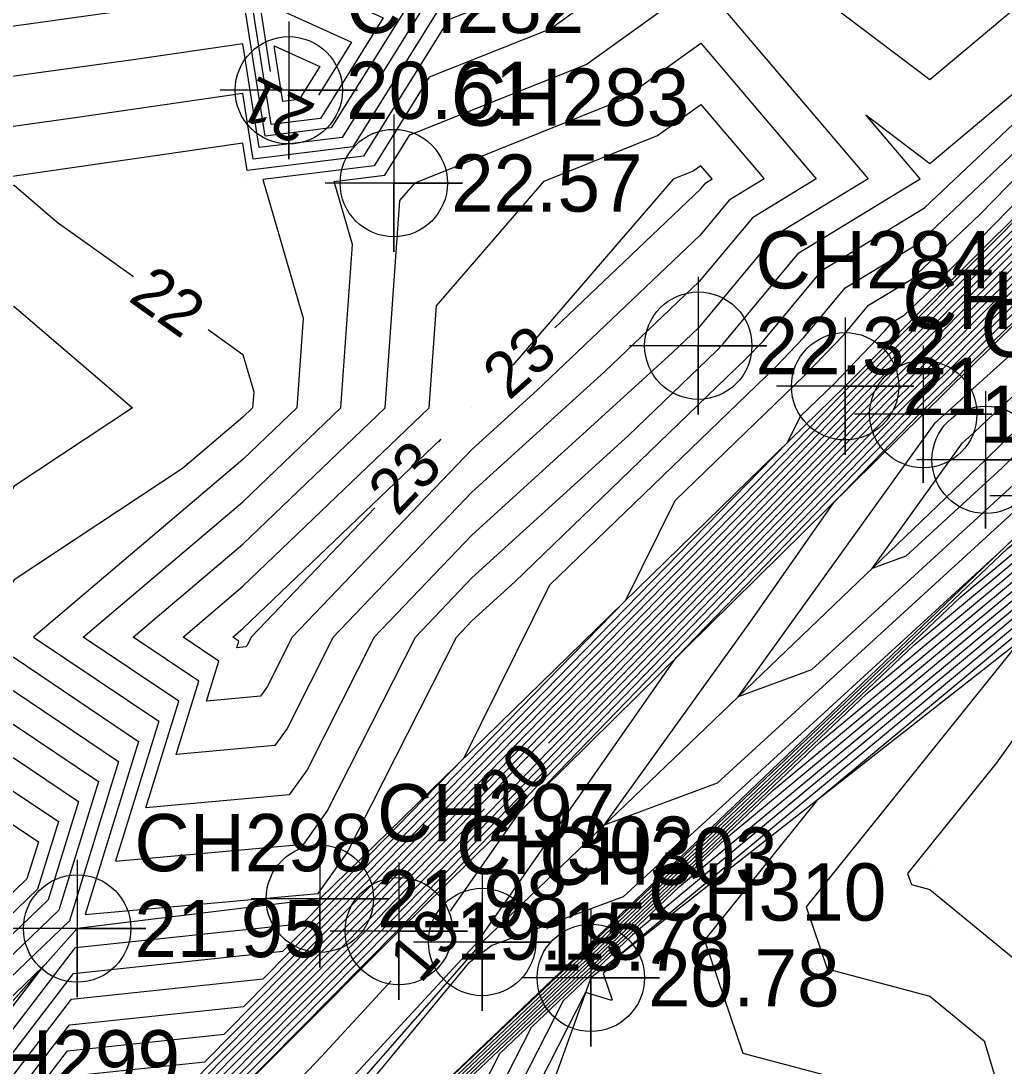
# Model space of a CAD drawing. Extents: x 2531902 to 2533249, y 715219 to 716099.
# Drawn here: x 2532990.3 to 2533033.24, y 715761.27 to 715806.9 of the extents above; entities that cross this region are included whole.
import ezdxf

# ---------------------------------------------------------------- set-up
doc = ezdxf.new("R2010")
doc.units = 0
for name, color, linetype in [('DTM Contours Major', 7, 'Continuous'), ('DTM Contours Major Text', 7, 'Continuous'), ('DTM Contours Minor', 7, 'Continuous'), ('Exist DTM Breakline', 7, 'Continuous'), ('Exist DTM Breakline Cogo Elevation', 7, 'Continuous'), ('Exist DTM Breakline Cogo Number', 7, 'Continuous'), ('Exist DTM Breakline Cogo Point CELL', 7, 'Continuous'), ('Exist DTM Drainline', 7, 'Continuous'), ('Exist DTM Drainline Cogo Elevation', 7, 'Continuous'), ('Exist DTM Drainline Cogo Number', 7, 'Continuous'), ('Exist DTM Drainline Cogo Point CELL', 7, 'Continuous'), ('Exist DTM QL2 LIDAR Elevation Point', 7, 'Continuous'), ('Exist DTM Regular Point CELL', 7, 'Continuous'), ('Exist DTM Regular Point Cogo Elevation', 7, 'Continuous'), ('Exist DTM Regular Point Cogo Number', 7, 'Continuous')]:
    doc.layers.add(name, color=color, linetype=linetype)

msp = doc.modelspace()

# ---------------------------------------------------------------- linework, layer by layer
at = {"layer": 'DTM Contours Major'}
for points in [[(2533085.587, 715843.684), (2533078.325, 715839.571), (2533075.832, 715838.696), (2533072.526, 715834.489), (2533062.673, 715824.977), (2533051.181, 715813.41), (2533041.576, 715804.106), (2533029.847, 715792.318), (2533029.205, 715791.695), (2533027.895, 715790.378), (2533015.561, 715777.627), (2533013.348, 715775.36)], [(2533080.807, 715836.843), (2533077.595, 715835.024), (2533074.015, 715833.767), (2533073.676, 715833.335), (2533054.852, 715815.162), (2533052.148, 715812.44), (2533034.586, 715795.428), (2533030.67, 715791.493), (2533029.541, 715790.397), (2533029.097, 715789.95), (2533012.049, 715772.325), (2533009.123, 715768.142), (2533009.05, 715768.032)], [(2533013.476, 715830), (2533013.132, 715826.868), (2533013.628, 715820), (2533014.116, 715815.884), (2533014.5, 715810), (2533011.885, 715808.115), (2533008.978, 715806.953), (2533005.261, 715800.99), (2533000.188, 715800.363), (2533000, 715801.564), (2532990.129, 715800.129), (2532989.942, 715800.104), (2532980.233, 715800.868), (2532979.778, 715800.822), (2532979.481, 715800.116), (2532979.048, 715799.048), (2532980, 715799.201), (2532981.992, 715798.008), (2532990, 715799.73), (2532991.885, 715798.115), (2532995.218, 715795.741)], [(2533008.764, 715758.562), (2533009.843, 715760.678), (2533014.663, 715765.254), (2533014.672, 715765.262), (2533023.159, 715773.32), (2533037.158, 715784.95), (2533037.66, 715785.451), (2533038.413, 715786.237), (2533049.753, 715797.548), (2533059.385, 715807.549), (2533072.253, 715820.374), (2533080.039, 715828.42)], [(2532979.452, 715750.737), (2532987.302, 715755.373), (2532992.336, 715761.936), (2532999.18, 715762.665), (2533004.55, 715768.086), (2533005.491, 715769.05), (2533005.991, 715769.568), (2533023.643, 715787.653), (2533026.693, 715790.807), (2533028.87, 715792.994), (2533029.024, 715793.143), (2533048.566, 715812.783), (2533050.214, 715814.379), (2533052.379, 715816.558)], [(2532977.504, 715809.832), (2532977.352, 715809.816), (2532973.798, 715801.389), (2532970.731, 715793.825), (2532968.124, 715787.575), (2532970, 715785.169), (2532977.166, 715790), (2532980, 715790.458), (2532980.764, 715790), (2532980, 715788.686), (2532972.904, 715780), (2532980, 715771.928), (2532985.876, 715774.124), (2532990, 715771.778), (2532991.063, 715771.063), (2532990.562, 715769.444), (2532989.08, 715768.02), (2532980.11, 715759.945), (2532978.063, 715751.479)], [(2532998.475, 715793.42), (2533000, 715792.334), (2533000.473, 715790.706), (2533000.423, 715790), (2533000, 715789.595), (2532997.359, 715787.359), (2532990, 715782.5), (2532988.424, 715780), (2532990, 715779.104), (2532995.444, 715775.444), (2532993.105, 715767.885), (2533003.288, 715768.805), (2533004.549, 715770.578), (2533009.322, 715780), (2533010, 715780.707), (2533011.877, 715782.415), (2533021.968, 715792.145), (2533022.732, 715792.939), (2533025.293, 715796.017), (2533029.762, 715798.732), (2533036.988, 715805.552), (2533038.98, 715807.592)], [(2533000.72, 715807.795), (2533004.742, 715805.97), (2533003.302, 715803.66)], [(2533001.204, 715804.694), (2533000.72, 715807.795)], [(2533060.482, 715806.755), (2533042.787, 715788.38), (2533039.908, 715785.508), (2533038.536, 715784.076), (2533038.417, 715783.957), (2533025.075, 715772.872), (2533020.164, 715766.763), (2533021.834, 715761.834), (2533028.75, 715760), (2533021.01, 715758.99), (2533020, 715758.992), (2533018.095, 715757.652), (2533013.058, 715759.189), (2533006.986, 715747.286), (2533006.768, 715746.357)], [(2533020.218, 715799.836), (2533020.489, 715800), (2533020, 715800.576), (2533019.665, 715800.335), (2533018.788, 715799.984), (2533011.785, 715791.866)], [(2533013.617, 715793.503), (2533019.993, 715799.565), (2533020.218, 715799.836)], [(2533006.472, 715764.984), (2533003.425, 715761.69), (2532993.835, 715751.621), (2532994.572, 715747.516), (2532999.056, 715743.739), (2533002.894, 715754.927), (2533003.116, 715755.194), (2533003.581, 715755.554), (2533013.979, 715765.427), (2533013.979, 715765.427), (2533033.397, 715783.864), (2533035.899, 715785.943), (2533036.784, 715786.825), (2533036.918, 715786.965), (2533046.121, 715796.145)], [(2532999.824, 715779.824), (2532999.562, 715780), (2533000, 715780.37), (2533008.641, 715788.641), (2533008.534, 715788.529)], [(2533005.766, 715785.641), (2533000.36, 715780), (2533000.176, 715779.636), (2533000.127, 715779.568), (2532999.734, 715779.532), (2532999.824, 715779.824)], [(2533010.555, 715772.498), (2533007.237, 715769.099), (2533006.203, 715768.027), (2533005.772, 715767.585), (2532994.914, 715756.625), (2532991.892, 715756.303), (2532989.669, 715753.405), (2532982.4, 715749.112), (2532985.539, 715745.687), (2532986.15, 715740.796), (2532990.229, 715734.139), (2532992.557, 715732.707), (2532999.985, 715732.227), (2533009.18, 715731.631), (2533002.89, 715742.242), (2533004.978, 715751.14), (2533006.946, 715754.999)], [(2532984.936, 715757.342), (2532991.292, 715765.629), (2532989.621, 715764.023)]]:
    msp.add_lwpolyline(points, dxfattribs=at)
at = {"layer": 'DTM Contours Minor'}
for points in [[(2533015.773, 715771.784), (2533022.151, 715780.652), (2533025.807, 715785.88), (2533029.577, 715789.779), (2533029.676, 715789.877), (2533030.999, 715791.163), (2533031.79, 715791.958), (2533042.258, 715802.098), (2533049.87, 715808.942), (2533052.953, 715811.863), (2533066.991, 715824.68), (2533075.158, 715832.451), (2533077.303, 715833.205), (2533078.895, 715834.106), (2533078.665, 715832.506), (2533078.282, 715830.231), (2533064.99, 715816.854), (2533057.137, 715808.963), (2533041.884, 715793.61), (2533035.994, 715787.69), (2533035.267, 715786.958), (2533034.852, 715786.542), (2533020.715, 715773.614), (2533015.773, 715771.784)], [(2533030.23, 715789.352), (2533031.368, 715790.375), (2533031.741, 715790.725), (2533044.287, 715802.006), (2533054.056, 715811.26), (2533062.22, 715818.714), (2533076.103, 715831.925), (2533077.157, 715832.295), (2533077.939, 715832.738), (2533077.826, 715831.952), (2533077.638, 715830.834), (2533071.107, 715824.261), (2533056.488, 715809.573), (2533047.618, 715800.644), (2533035.342, 715788.307), (2533034.873, 715787.835), (2533034.004, 715786.962), (2533024.831, 715778.573), (2533021.624, 715777.386), (2533030.23, 715789.352)], [(2533023.907, 715830), (2533022.077, 715822.077), (2533022.993, 715820), (2533021.046, 715818.954), (2533022.511, 715810), (2533030, 715804.336), (2533036.745, 715810)], [(2533031.424, 715788.479), (2533031.947, 715788.948), (2533033.074, 715790.008), (2533038.704, 715795.07), (2533055.158, 715810.656), (2533057.448, 715812.747), (2533075.297, 715829.733), (2533055.84, 715810.183), (2533053.352, 715807.678), (2533034.69, 715788.923), (2533034.48, 715788.711), (2533033.156, 715787.382), (2533028.947, 715783.532), (2533027.476, 715782.988), (2533031.424, 715788.479)], [(2532986.829, 715755.767), (2532992.425, 715763.063), (2533000.033, 715763.873), (2533004.306, 715768.186), (2533005.349, 715769.254), (2533005.742, 715769.662), (2533025.259, 715789.658), (2533026.453, 715790.893), (2533028.802, 715793.254), (2533028.859, 715793.308), (2533049.964, 715814.518)], [(2532986.356, 715756.161), (2532992.514, 715764.189), (2533000.886, 715765.081), (2533004.062, 715768.286), (2533005.206, 715769.459), (2533005.493, 715769.756), (2533023.779, 715788.491), (2533024.345, 715789.636), (2533025.838, 715791.075), (2533028.023, 715793.347), (2533028.337, 715793.725), (2533028.886, 715794.059), (2533029.774, 715794.896), (2533048.162, 715813.734)], [(2532985.883, 715756.555), (2532992.603, 715765.316), (2533001.74, 715766.288), (2533003.818, 715768.386), (2533005.064, 715769.663), (2533005.244, 715769.85), (2533016.72, 715781.608), (2533018.874, 715785.96), (2533024.548, 715791.432), (2533026.259, 715793.211), (2533027.322, 715794.489), (2533029.178, 715795.616), (2533032.179, 715798.448), (2533046.243, 715812.856)], [(2533016.6, 715768.655), (2533011.353, 715766.712), (2533010.868, 715766.533), (2533009.843, 715765.74), (2532998.823, 715752.424), (2532997.639, 715748.973), (2532996.256, 715750.138), (2532996.029, 715751.404), (2532998.987, 715754.51), (2533010.27, 715766.707), (2533010.33, 715766.793), (2533010.564, 715767.143), (2533018.928, 715779.103), (2533029.337, 715789.864), (2533029.609, 715790.137), (2533030.835, 715791.328), (2533033.188, 715793.693), (2533052.341, 715812.246)], [(2532965.758, 715754.242), (2532970, 715758.737), (2532976.817, 715756.817), (2532977.934, 715754.092), (2532976.545, 715748.347), (2532987.776, 715754.98), (2532992.247, 715760.81), (2532998.327, 715761.457), (2533004.795, 715767.986), (2533005.634, 715768.845), (2533006.24, 715769.474), (2533022.026, 715785.648), (2533026.934, 715790.721), (2533028.937, 715792.734), (2533029.188, 715792.978), (2533047.168, 715811.047)], [(2533018.215, 715810), (2533013.441, 715806.559), (2533008.135, 715804.437), (2533005.729, 715800.578), (2533000.868, 715799.976), (2533002.629, 715793.92), (2533002.351, 715790), (2533000, 715787.75), (2532990.846, 715780), (2532996.32, 715776.32), (2532994.431, 715770.214), (2533002.656, 715770.958), (2533003.674, 715772.39), (2533007.53, 715780), (2533010, 715782.578), (2533016.839, 715788.8), (2533020.678, 715792.501), (2533020.969, 715792.803), (2533024.278, 715796.78), (2533029.577, 715800), (2533027.208, 715802.792), (2533030, 715800.68), (2533034.245, 715804.245)], [(2533000.071, 715809.783), (2533006.129, 715807.034), (2533003.392, 715802.642), (2533001.228, 715802.374), (2533000.071, 715809.783)], [(2532960, 715751.662), (2532968.121, 715751.879), (2532970, 715753.87), (2532973.02, 715753.02), (2532975.47, 715747.043), (2532975.468, 715747.038), (2532988.249, 715754.586), (2532992.158, 715759.683), (2532997.474, 715760.249), (2533005.039, 715767.885), (2533005.776, 715768.641), (2533006.489, 715769.38), (2533020.41, 715783.643), (2533027.174, 715790.636), (2533029.004, 715792.474), (2533029.353, 715792.813), (2533045.77, 715809.312)], [(2533009.822, 715809.469), (2533004.794, 715801.403), (2533000.448, 715800.866), (2533000, 715803.732), (2532992.666, 715802.666), (2532988.811, 715802.133), (2532980.743, 715802.769), (2532979.293, 715802.62), (2532978.344, 715800.371), (2532976.962, 715796.962), (2532980, 715797.453), (2532986.354, 715793.646), (2532990, 715794.43), (2532995.172, 715790), (2532990, 715786.585), (2532985.848, 715780), (2532990, 715777.638), (2532994.568, 715774.568), (2532992.416, 715767.611), (2532986.048, 715761.494), (2532982.824, 715758.591)], [(2533008.905, 715809.161), (2533004.326, 715801.816), (2533000.708, 715801.368), (2533000, 715805.9), (2532995.203, 715805.203), (2532987.68, 715804.163), (2532981.254, 715804.669), (2532978.808, 715804.419), (2532977.208, 715800.625), (2532974.877, 715794.877), (2532980, 715795.704), (2532989.521, 715790), (2532988.856, 715788.856), (2532983.272, 715780), (2532990, 715776.173), (2532993.692, 715773.692), (2532991.952, 715768.069), (2532986.806, 715763.125), (2532982.145, 715758.93)], [(2533006.196, 715800.165), (2533007.291, 715801.922), (2533014.997, 715805.003), (2533020, 715808.609), (2533027.305, 715800), (2533023.263, 715797.544), (2533019.898, 715793.5), (2533018.748, 715792.407), (2533010, 715784.448), (2533005.737, 715780), (2533002.8, 715774.201), (2533002.023, 715773.11), (2532995.757, 715772.544), (2532997.196, 715777.196), (2532993.025, 715780), (2533000, 715785.905), (2533004.278, 715790), (2533004.785, 715797.134), (2533003.984, 715799.891), (2533006.196, 715800.165)], [(2532977.837, 715808.017), (2532974.935, 715801.134), (2532970.706, 715790.706), (2532980, 715792.206), (2532983.683, 715790), (2532980, 715783.664), (2532977.006, 715780), (2532980, 715776.595), (2532982.479, 715777.521), (2532990, 715773.243), (2532991.939, 715771.939), (2532991.026, 715768.986), (2532988.322, 715766.388), (2532980.788, 715759.607)], [(2533007.517, 715808.097), (2533003.859, 715802.229), (2533000.968, 715801.871), (2533000, 715808.068)], [(2532997.74, 715807.74), (2532986.548, 715806.193), (2532981.764, 715806.57), (2532978.323, 715806.218), (2532976.071, 715800.88), (2532972.791, 715792.791), (2532980, 715793.955), (2532986.602, 715790), (2532981.884, 715781.884), (2532980.696, 715780), (2532990, 715774.708), (2532992.816, 715772.816), (2532991.489, 715768.528), (2532987.564, 715764.757), (2532981.467, 715759.268)], [(2533044.372, 715807.577), (2533029.518, 715792.648), (2533029.071, 715792.215), (2533027.414, 715790.55), (2533018.794, 715781.637), (2533006.738, 715769.286), (2533005.918, 715768.436), (2533005.283, 715767.785), (2532996.621, 715759.041)], [(2532998.072, 715778.072), (2532995.204, 715780), (2533000, 715784.06), (2533006.206, 715790), (2533006.85, 715799.062), (2533007.514, 715799.832), (2533016.553, 715803.447), (2533020, 715805.931), (2533025.033, 715800), (2533022.248, 715798.308), (2533019.93, 715795.522), (2533015.801, 715791.596), (2533010, 715786.318), (2533003.945, 715780), (2533001.925, 715776.013), (2533001.391, 715775.263), (2532997.082, 715774.873), (2532998.072, 715778.072)], [(2533042.974, 715805.841), (2533029.682, 715792.483), (2533029.138, 715791.955), (2533027.655, 715790.464), (2533017.177, 715779.632), (2533006.988, 715769.192), (2533006.061, 715768.232), (2533005.527, 715767.685), (2532995.767, 715757.833)], [(2533001.369, 715805.807), (2533003.354, 715804.907), (2533002.457, 715803.468), (2533001.748, 715803.38), (2533001.369, 715805.807)], [(2532998.948, 715778.948), (2532997.383, 715780), (2533000, 715782.215), (2533008.133, 715790), (2533008.45, 715794.459), (2533013.151, 715799.908), (2533018.109, 715801.891), (2533020, 715803.254), (2533022.761, 715800), (2533021.233, 715799.072), (2533019.962, 715797.544), (2533012.854, 715790.785), (2533010, 715788.189), (2533002.152, 715780), (2533001.05, 715777.825), (2533000.759, 715777.415), (2532998.408, 715777.203), (2532998.948, 715778.948)], [(2532985.409, 715756.948), (2532992.692, 715766.442), (2533002.593, 715767.496), (2533003.573, 715768.486), (2533004.922, 715769.868), (2533004.995, 715769.944), (2533009.662, 715774.725), (2533013.402, 715782.285), (2533023.258, 715791.788), (2533024.496, 715793.075), (2533026.307, 715795.253), (2533029.47, 715797.174), (2533034.584, 715802)], [(2533040.178, 715802.37), (2533030.011, 715792.153), (2533029.273, 715791.436), (2533028.135, 715790.293), (2533013.944, 715775.622), (2533007.486, 715769.005), (2533006.346, 715767.823), (2533006.016, 715767.485), (2532994.061, 715755.417)], [(2533038.78, 715800.635), (2533030.176, 715791.988), (2533029.34, 715791.176), (2533028.376, 715790.207), (2533012.328, 715773.617), (2533007.735, 715768.911), (2533006.488, 715767.618), (2533006.26, 715767.385), (2532993.208, 715754.209)], [(2533037.382, 715798.899), (2533030.341, 715791.823), (2533029.407, 715790.916), (2533028.616, 715790.121), (2533010.712, 715771.611), (2533007.984, 715768.817), (2533006.63, 715767.414), (2533006.504, 715767.285), (2532992.355, 715753.001)], [(2533035.984, 715797.164), (2533030.505, 715791.658), (2533029.474, 715790.657), (2533028.856, 715790.036), (2533009.095, 715769.606), (2533008.233, 715768.723), (2533006.773, 715767.209), (2533006.749, 715767.185), (2532993.991, 715754.306), (2532991.64, 715751.838), (2532992.888, 715744.893), (2532997.864, 715740.701), (2532999.285, 715739.827), (2532999.934, 715739.785), (2533000.738, 715739.733), (2533000.188, 715740.66), (2533003.371, 715754.223), (2533004.328, 715756.099), (2533014.116, 715765.392), (2533014.118, 715765.394), (2533031.349, 715781.755), (2533036.151, 715785.744)], [(2533005.707, 715757.244), (2533014.252, 715765.358), (2533014.256, 715765.361), (2533029.302, 715779.646), (2533036.403, 715785.546)], [(2533035.444, 715785.972), (2533033.02, 715783.671), (2533016.6, 715768.655)], [(2533007.086, 715758.389), (2533014.389, 715765.323), (2533014.395, 715765.328), (2533027.254, 715777.537), (2533036.655, 715785.347)], [(2533008.464, 715759.533), (2533014.526, 715765.289), (2533014.533, 715765.295), (2533025.207, 715775.429), (2533036.906, 715785.148)], [(2533005.379, 715750.369), (2533011.222, 715761.823), (2533014.799, 715765.22), (2533014.811, 715765.228), (2533021.111, 715771.211), (2533037.41, 715784.751)], [(2533037.914, 715784.354), (2533017.016, 715766.994), (2533015.088, 715765.162), (2533015.073, 715765.15), (2533013.979, 715764.112), (2533006.183, 715748.827), (2533004.916, 715743.428), (2533011.997, 715731.483), (2533014.396, 715730.343), (2533014.965, 715728.527), (2533020, 715720.286), (2533020.138, 715720.275), (2533031.631, 715722.45)], [(2533005.781, 715749.598), (2533012.601, 715762.967), (2533014.936, 715765.185), (2533014.949, 715765.195), (2533019.064, 715769.102), (2533037.662, 715784.553)], [(2533038.165, 715784.155), (2533016.248, 715765.948), (2533015.731, 715765.305), (2533016.12, 715764.158), (2533016.118, 715764.135), (2533014.965, 715764.487), (2533006.584, 715748.056), (2533005.591, 715743.824), (2533011.143, 715734.458), (2533015.565, 715732.358), (2533016.615, 715729.01), (2533020, 715723.468), (2533021.668, 715723.337), (2533031.378, 715725.174)], [(2533039.005, 715783.046), (2533032.907, 715774.504), (2533029.03, 715769.681), (2533029.195, 715769.195), (2533030, 715768.982), (2533034.937, 715764.937)], [(2533033.901, 715779.797), (2533024.597, 715768.222), (2533025.514, 715765.514), (2533030, 715764.325), (2533032.377, 715762.377), (2533033.087, 715760), (2533030, 715757.871), (2533023.038, 715756.962), (2533020, 715756.968), (2533014.272, 715752.939), (2533011.15, 715753.891), (2533007.388, 715746.515), (2533006.942, 715744.614), (2533009.434, 715740.41), (2533017.903, 715736.387), (2533019.913, 715729.975), (2533020, 715729.833), (2533024.729, 715729.459), (2533030.872, 715730.621)]]:
    msp.add_lwpolyline(points, dxfattribs=at)
at = {"layer": 'Exist DTM Breakline'}
for points in [[(2533071.263, 715835.756), (2533026.299, 715790.948), (2533003.355, 715768.576), (2532992.757, 715767.273), (2532984.347, 715757.832), (2532975.467, 715747.036), (2532972.43, 715743.961)], [(2533073.808, 715833.204), (2533029.714, 715789.73), (2533006.807, 715767.161), (2532991.54, 715751.848), (2532990.629, 715741.375)], [(2533079.183, 715829.387), (2533035.625, 715786.159), (2533002.978, 715754.978), (2532999.93, 715740.509), (2532990.629, 715741.375)], [(2533082.767, 715827.756), (2533038.809, 715783.648), (2533015.193, 715765.12), (2533008.042, 715745.259), (2533013.01, 715727.955)]]:
    msp.add_lwpolyline(points, dxfattribs=at)
at = {"layer": 'Exist DTM Breakline Cogo Point CELL'}
for points in [[(2533026.299, 715793.948), (2533026.299, 715787.948), (2533026.299, 715790.948), (2533029.299, 715790.948), (2533023.299, 715790.948)], [(2533029.714, 715792.73), (2533029.714, 715786.73), (2533029.714, 715789.73), (2533032.714, 715789.73), (2533026.714, 715789.73)], [(2533035.625, 715789.159), (2533035.625, 715783.159), (2533035.625, 715786.159), (2533038.625, 715786.159), (2533032.625, 715786.159)], [(2533003.355, 715771.576), (2533003.355, 715765.576), (2533003.355, 715768.576), (2533006.355, 715768.576), (2533000.355, 715768.576)], [(2532992.757, 715770.273), (2532992.757, 715764.273), (2532992.757, 715767.273), (2532995.757, 715767.273), (2532989.757, 715767.273)], [(2533006.807, 715770.161), (2533006.807, 715764.161), (2533006.807, 715767.161), (2533009.807, 715767.161), (2533003.807, 715767.161)], [(2533015.193, 715768.12), (2533015.193, 715762.12), (2533015.193, 715765.12), (2533018.193, 715765.12), (2533012.193, 715765.12)]]:
    msp.add_lwpolyline(points, dxfattribs=at)
for centre in [(2533026.299, 715790.948), (2533029.714, 715789.73), (2533003.355, 715768.576), (2532992.757, 715767.273), (2533006.807, 715767.161), (2533015.193, 715765.12)]:
    msp.add_circle(centre, 2.344, dxfattribs=at)
at = {"layer": 'Exist DTM Drainline'}
msp.add_lwpolyline([(2533077.016, 715831.416), (2533032.437, 715787.738), (2533010.445, 715766.684), (2532997.007, 715751.307)], dxfattribs=at)
at = {"layer": 'Exist DTM Drainline Cogo Point CELL'}
for points in [[(2533032.437, 715790.738), (2533032.437, 715784.738), (2533032.437, 715787.738), (2533035.437, 715787.738), (2533029.437, 715787.738)], [(2533010.445, 715769.684), (2533010.445, 715763.684), (2533010.445, 715766.684), (2533013.445, 715766.684), (2533007.445, 715766.684)]]:
    msp.add_lwpolyline(points, dxfattribs=at)
for centre in [(2533032.437, 715787.738), (2533010.445, 715766.684)]:
    msp.add_circle(centre, 2.344, dxfattribs=at)
at = {"layer": 'Exist DTM QL2 LIDAR Elevation Point'}
for p, q in [((2533000, 715800), (2533000, 715800)), ((2533020, 715800), (2533020, 715800)), ((2533030, 715800), (2533030, 715800)), ((2533000, 715790), (2533000, 715790)), ((2533010, 715790), (2533010, 715790)), ((2533000, 715780), (2533000, 715780)), ((2533010, 715780), (2533010, 715780)), ((2533030, 715770), (2533030, 715770))]:
    msp.add_line(p, q, dxfattribs=at)
at = {"layer": 'Exist DTM Regular Point CELL'}
for points in [[(2533002.001, 715806.87), (2533002.001, 715800.87), (2533002.001, 715803.87), (2533005.001, 715803.87), (2532999.001, 715803.87)], [(2533006.587, 715802.82), (2533006.587, 715796.82), (2533006.587, 715799.82), (2533009.587, 715799.82), (2533003.587, 715799.82)], [(2533019.886, 715795.72), (2533019.886, 715789.72), (2533019.886, 715792.72), (2533022.886, 715792.72), (2533016.886, 715792.72)]]:
    msp.add_lwpolyline(points, dxfattribs=at)
for centre in [(2533002.001, 715803.87), (2533006.587, 715799.82), (2533019.886, 715792.72)]:
    msp.add_circle(centre, 2.344, dxfattribs=at)

# ---------------------------------------------------------------- texts
at = {"layer": 'DTM Contours Major Text'}
for s, rotation, p in [('21', 153.7582, (2533003.248, 715803.223)), ('22', 324.5335, (2532994.939, 715794.712)), ('23', 41.7757, (2533011.619, 715790.293)), ('23', 46.2182, (2533006.744, 715785.217)), ('20', 45.6949, (2533011.529, 715772.064)), ('19', 49.7835, (2533007.755, 715764.814))]:
    msp.add_text(s, height=2, rotation=rotation, dxfattribs=at).set_placement(p)
at = {"layer": 'Exist DTM Breakline Cogo Elevation'}
for s, p in [('21.33', (2533028.799, 715789.698)), ('18.49', (2533032.214, 715788.48)), ('21.98', (2533005.855, 715767.326)), ('21.95', (2532995.257, 715766.023)), ('19.15', (2533009.307, 715765.911)), ('20.78', (2533017.693, 715763.87))]:
    msp.add_text(s, height=2.5, dxfattribs=at).set_placement(p)
at = {"layer": 'Exist DTM Breakline Cogo Number'}
for s, p in [('CH285', (2533028.799, 715793.448)), ('CH286', (2533032.214, 715792.23)), ('CH297', (2533005.855, 715771.076)), ('CH298', (2532995.257, 715769.773)), ('CH302', (2533009.307, 715769.661)), ('CH310', (2533017.693, 715767.62)), ('CH299', (2532986.847, 715760.332))]:
    msp.add_text(s, height=2.5, dxfattribs=at).set_placement(p)
at = {"layer": 'Exist DTM Drainline Cogo Elevation'}
msp.add_text('18.78', height=2.5, dxfattribs=at).set_placement((2533012.945, 715765.434))
at = {"layer": 'Exist DTM Drainline Cogo Number'}
msp.add_text('CH303', height=2.5, dxfattribs=at).set_placement((2533012.945, 715769.184))
at = {"layer": 'Exist DTM Regular Point Cogo Elevation'}
for s, p in [('20.61', (2533004.501, 715802.62)), ('22.57', (2533009.087, 715798.57)), ('22.32', (2533022.386, 715791.47))]:
    msp.add_text(s, height=2.5, dxfattribs=at).set_placement(p)
at = {"layer": 'Exist DTM Regular Point Cogo Number'}
for s, p in [('CH282', (2533004.501, 715806.37)), ('CH283', (2533009.087, 715802.32)), ('CH284', (2533022.386, 715795.22))]:
    msp.add_text(s, height=2.5, dxfattribs=at).set_placement(p)

doc.saveas('drawing.dxf')
